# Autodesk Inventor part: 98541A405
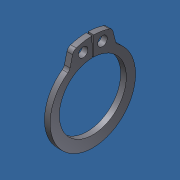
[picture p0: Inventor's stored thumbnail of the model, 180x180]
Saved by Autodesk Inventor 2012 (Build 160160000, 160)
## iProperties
Created: 2013-11
Part Number: 98541A405
Material: Steel
Document SubType Name: Modeling
Designer: Admin
Density: 7.85 g/cm^3
Mass: 0.633664 g
Surface Area: 2.67094 cm^2
Volume: 0.0807215 cm^3
Translation Standard: STEP AP203
FileName: 98541A405.step
PreProcessor: SolidWorks 2007
PostProcessor: Build: 160, Release: 2012 RTM - Date: Tue 03/01/2011
Sent Units: inch
Uncertainty: 1e-05
Author: Admin
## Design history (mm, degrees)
node "98541A4051"
node "Base1"
body "Solid1"
